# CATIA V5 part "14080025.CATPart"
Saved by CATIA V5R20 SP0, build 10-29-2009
Part number: 14080025
Definition: NONE
Nomenclature: 14080025
Source: Unknown
Description: 14080025
Bounding box of the stored display mesh (mm): x -12.5 to 50, y -54 to 43.912, z -44.1 to 44.1
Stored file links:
  C:\Users\Utente\Desktop\IO LAVORO\3D X SITO CF\X SITO\PLASTICA\RF2\14080025.CATPart
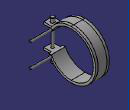
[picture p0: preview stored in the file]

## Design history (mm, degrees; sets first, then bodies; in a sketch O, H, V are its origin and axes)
Body1 "14080025" (main body)
  Solid1: solid without history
